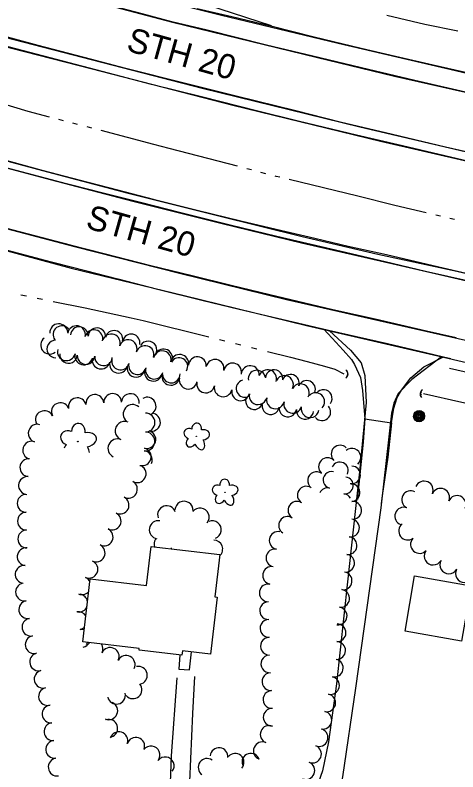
# Model space of a CAD drawing. Extents: x 588843 to 2552415, y 180129 to 269402.
# Drawn here: x 596827.9 to 597009.4, y 184077.1 to 184387.3 of the extents above; entities that cross this region are included whole.
import ezdxf

# ---------------------------------------------------------------- set-up
doc = ezdxf.new("R2010")
doc.units = 0
for name, color, linetype in [('Default', 7, 'Continuous'), ('E_BLD', 7, 'Continuous'), ('E_DRN', 7, 'Continuous'), ('E_DWY', 7, 'Continuous'), ('E_LAND_TreeLine_P', 7, 'Continuous'), ('E_LAND_Vegetation', 7, 'Continuous'), ('E_MISCPROP', 7, 'Continuous'), ('E_PATH_Sidewalk', 7, 'Continuous'), ('E_RDWY', 7, 'Continuous'), ('E_RDWY_Gravel', 7, 'Continuous'), ('E_RDWY_Text', 7, 'Continuous'), ('E_WTR_P', 7, 'Continuous')]:
    doc.layers.add(name, color=color, linetype=linetype)

# ---------------------------------------------------------------- blocks, each defined once
blk = doc.blocks.new('POLE')
at = {"layer": 'Default'}
for radius in [4.46, 3.35, 2.23, 1.12]:
    blk.add_circle((0, 0), radius, dxfattribs=at)
blk = doc.blocks.new('CULV2')
at = {"layer": 'E_DRN'}
blk.add_arc((19.7, 14.8), 24.6, 216.8699, 323.1301, dxfattribs=at)
blk = doc.blocks.new('DTRE')
at = {"layer": 'Default'}
blk.add_circle((-0.18, 0), 0.183, dxfattribs=at)
for centre, major_axis, ratio in [((-1.87, 5.32), (1.36, -4.98), 0.782863), ((4.06, 2.74), (-5.27, -2.93), 0.691916), ((-5.87, 0.15), (4.93, -0.12), 0.832022), ((-2.49, -5.24), (1.8, 4.86), 0.716896), ((3.54, -3.71), (-5.01, 4.58), 0.560249)]:
    blk.add_ellipse(centre, major_axis=major_axis, ratio=ratio, start_param=1.570796, end_param=4.712389, dxfattribs=at)
blk = doc.blocks.new('CULV2_4')
at = {"layer": 'E_DRN'}
blk.add_arc((65, 48), 80.7, 216.8699, 323.1301, dxfattribs=at)
blk = doc.blocks.new('POLE_3')
at = {"layer": 'E_MISCPROP'}
for radius in [14.6, 11, 7.32, 3.66]:
    blk.add_circle((0, 0), radius, dxfattribs=at)
blk = doc.blocks.new('DTRE_4')
at = {"layer": 'E_LAND_Vegetation'}
blk.add_circle((-0.6, 0), 0.601, dxfattribs=at)
for centre, major_axis, ratio in [((-6.1, 17.5), (4.5, -16.3), 0.782863), ((13.3, 9), (-17.3, -9.6), 0.691916), ((-19.3, 0.5), (16.2, -0.4), 0.832022), ((-8.2, -17.2), (5.9, 15.9), 0.716896), ((11.6, -12.2), (-16.4, 15), 0.560249)]:
    blk.add_ellipse(centre, major_axis=major_axis, ratio=ratio, start_param=1.570796, end_param=4.712389, dxfattribs=at)

msp = doc.modelspace()

# ---------------------------------------------------------------- linework, layer by layer
at = {"layer": 'E_BLD'}
for points in [[(596883.77, 184169.53), (596911.85, 184166.18), (596909.79, 184148.86), (596910.81, 184148.73), (596908.02, 184125.35), (596896.51, 184126.73), (596896.3, 184124.94), (596878.76, 184127.03), (596878.84, 184127.64), (596855.68, 184130.4), (596858.76, 184156.21), (596881.85, 184153.46)], [(597010.97, 184130.74), (596987.79, 184134.73), (596991.69, 184157.41), (597014.87, 184153.42)]]:
    msp.add_lwpolyline(points, close=True, dxfattribs=at)
at = {"layer": 'E_DWY'}
for points in [[(596954.33, 184258.7), (596957.91, 184254.93), (596962.44, 184250.04), (596965.86, 184246.21), (596967.08, 184244.07), (596969.51, 184238.75), (596970.35, 184233.4), (596971.32, 184221.9), (596982.29, 184220.26), (596983.2, 184226.22), (596984.61, 184230.54), (596986.35, 184233.61), (596990.14, 184238.65), (596995.44, 184243.18), (597003.56, 184247.25)], [(596956.85, 184257.89), (596965.4, 184249.99), (596969.75, 184244.8), (596971.27, 184239.65), (596971.88, 184228.55), (596969.06, 184200.1), (596964.26, 184154.96), (596959.64, 184113.14), (596956.45, 184089.42), (596953.89, 184077.51), (596950.34, 184067.35), (596946.51, 184058.42), (596942.86, 184053.96), (596937.47, 184048.93), (596929.11, 184045.67), (596919.51, 184044.02), (596912.14, 184046.27), (596905.02, 184048.65), (596903.2, 184050.84), (596900.38, 184060.03), (596899.5, 184073.2), (596900.78, 184101.02), (596901.62, 184116.24)], [(597002.73, 184247.31), (596990.58, 184237.99), (596985, 184232.28), (596983.25, 184228.24), (596982.22, 184224.11), (596977.82, 184185.38), (596967.46, 184111.39), (596962.14, 184075.02), (596959.65, 184064.88), (596955.17, 184049.82), (596949.6, 184038.43), (596946.07, 184031.73), (596941.32, 184027.48), (596936.01, 184024.63), (596926.24, 184023.87), (596918.41, 184025.61), (596911.03, 184028.17), (596904.65, 184033.62), (596899.86, 184041.04), (596894.78, 184051.17), (596891.23, 184061.51), (596891.99, 184083.69), (596894.43, 184115.71)], [(596971.32, 184221.9), (596970.57, 184212.24), (596968.5, 184191.1), (596968.24, 184188.79)], [(596982.29, 184220.26), (596980.77, 184206.14), (596978.4, 184190.36), (596977.99, 184187.08)]]:
    msp.add_lwpolyline(points, dxfattribs=at)
at = {"layer": 'E_LAND_TreeLine_P'}
for centre, radius, start, end in [((596845.83, 184257.15), 3.66, 2.2292, 182.2292), ((596847.1, 184256.38), 3.59, 36.9794, 216.9794), ((596853.08, 184256.3), 3.66, 349.694, 169.694), ((596854.24, 184255.99), 3.59, 356.2605, 176.2605), ((596861.41, 184255.52), 3.59, 356.2605, 176.2605), ((596860.23, 184254.69), 3.66, 346.488, 166.488), ((596867.34, 184252.95), 3.66, 341.2343, 161.2343), ((596868.49, 184254.45), 3.59, 348.3621, 168.3621), ((596875.53, 184253), 3.59, 348.3621, 168.3621), ((596842.09, 184252.05), 3.66, 127.6486, 307.6486), ((596844.57, 184250.48), 3.59, 90.4934, 270.4934), ((596874.28, 184250.59), 3.66, 340.5691, 160.5691), ((596882.46, 184250.11), 3.59, 328.9058, 148.9058), ((596848.94, 184249.37), 3.66, 166.3162, 346.3162), ((596881.21, 184248.19), 3.66, 343.0131, 163.0131), ((596888.23, 184246.08), 3.66, 346.8467, 166.8467), ((596888.84, 184246.84), 3.59, 334.0565, 154.0565), ((596849.83, 184248.2), 3.59, 176.1983, 356.1983), ((596856.06, 184247.63), 3.66, 166.3162, 346.3162), ((596856.99, 184247.73), 3.59, 176.1983, 356.1983), ((596863.19, 184245.93), 3.66, 166.8188, 346.8188), ((596864.16, 184247.25), 3.59, 176.1983, 356.1983), ((596871.11, 184245.48), 3.59, 164.9724, 344.9724), ((596895.4, 184244.56), 3.66, 350.5865, 170.5865), ((596895.1, 184243.31), 3.59, 330.5118, 150.5118), ((596902.65, 184243.59), 3.66, 355.619, 175.619), ((596909.9, 184242.53), 3.66, 348.0441, 168.0441), ((596870.33, 184244.26), 3.66, 166.8188, 346.8188), ((596877.47, 184242.59), 3.66, 167.0598, 347.0598), ((596878.05, 184243.61), 3.59, 164.9724, 344.9724), ((596917.08, 184241.03), 3.66, 349.5821, 169.5821), ((596924.32, 184239.97), 3.66, 356.1401, 176.1401), ((596884.61, 184240.95), 3.66, 167.0598, 347.0598), ((596884.99, 184241.75), 3.59, 164.9724, 344.9724), ((596891.76, 184239.31), 3.66, 167.5548, 347.5548), ((596891.95, 184240.15), 3.59, 181.2473, 1.2473), ((596927.05, 184238.22), 3.54, 9.5649, 189.5649), ((596931.44, 184238.3), 3.66, 342.0174, 162.0174), ((596934.09, 184238.39), 3.54, 356.2374, 176.2374), ((596940.87, 184236.49), 3.54, 340.7339, 160.7339), ((596898.91, 184237.73), 3.66, 167.5548, 347.5548), ((596906.07, 184236.15), 3.66, 167.5548, 347.5548), ((596922.1, 184234.21), 3.54, 105.1272, 285.1272), ((596938.36, 184235.91), 3.66, 332.6239, 152.6239), ((596947.5, 184233.99), 3.54, 337.8382, 157.8382), ((596913.23, 184234.56), 3.66, 167.2704, 347.2704), ((596920.38, 184232.94), 3.66, 167.2704, 347.2704), ((596944.86, 184232.53), 3.66, 332.2458, 152.2458), ((596954.33, 184230.27), 3.54, 323.5105, 143.5105), ((596860.62, 184228.15), 3.66, 2.983, 182.983), ((596867.92, 184228.53), 3.66, 2.983, 182.983), ((596875.21, 184228.49), 3.66, 353.5875, 173.5875), ((596882.05, 184227.02), 3.66, 299.548, 119.548), ((596927.52, 184231.31), 3.66, 166.7899, 346.7899), ((596951.17, 184228.87), 3.66, 315.6331, 135.6331), ((596846.48, 184224.77), 3.66, 26.5352, 206.5352), ((596853.45, 184226.8), 3.66, 12.499, 192.499), ((596876.13, 184223.81), 3.87, 49.1269, 229.1269), ((596925.95, 184229.21), 3.54, 160.5571, 340.5571), ((596932.7, 184227.11), 3.54, 172.4552, 352.4552), ((596934.66, 184229.63), 3.66, 166.7899, 346.7899), ((596941.76, 184227.8), 3.66, 164.9872, 344.9872), ((596839.93, 184221.5), 3.66, 26.5352, 206.5352), ((596939.73, 184226.18), 3.54, 172.4552, 352.4552), ((596946.76, 184225.27), 3.54, 173.759, 353.759), ((596948.85, 184225.98), 3.66, 170.1016, 350.1016), ((596953.75, 184224.67), 3.54, 220.8579, 40.8579), ((596881.36, 184220.32), 3.87, 270.1198, 90.1198), ((596883.82, 184220.43), 3.66, 255.0419, 75.0419), ((596836.97, 184215.93), 3.66, 71.9454, 251.9454), ((596872.8, 184216.9), 3.87, 67.7528, 247.7528), ((596881.31, 184212.59), 3.87, 262.3167, 82.3167), ((596881.93, 184213.36), 3.66, 255.0419, 75.0419), ((596834.7, 184208.98), 3.66, 71.9454, 251.9454), ((596869.87, 184209.75), 3.87, 67.7528, 243.9363), ((596880.04, 184206.3), 3.66, 255.0419, 75.0419), ((596961.15, 184207.39), 3.64, 45.1903, 225.1903), ((596966.02, 184206.06), 3.64, 310.1677, 130.1677), ((596880.28, 184204.93), 3.87, 338.7793, 82.3167), ((596956.01, 184202.22), 3.64, 45.1903, 225.1903), ((596833.57, 184201.8), 3.66, 85.5021, 265.5021), ((596961.05, 184200.66), 3.43, 334.313, 154.313), ((596877.96, 184199.32), 3.66, 240.7485, 60.7485), ((596951.5, 184196.5), 3.64, 52.7466, 232.7466), ((596957.62, 184196.78), 3.43, 76.8362, 256.8362), ((596965.83, 184198.84), 3.64, 267.0768, 87.0768), ((596832.99, 184194.51), 3.66, 85.5021, 265.5021), ((596963.14, 184194.54), 3.43, 263.4115, 83.4115), ((596874.38, 184192.94), 3.66, 240.7485, 60.7485), ((596947.3, 184190.56), 3.64, 58.212, 238.212), ((596956.05, 184190.1), 3.43, 76.8362, 156.5505), ((596965.64, 184191.56), 3.64, 275.4025, 95.4025), ((596995.63, 184192.61), 3.68, 336.3124, 156.3124), ((596832.45, 184187.22), 3.66, 91.0738, 271.0738), ((596962.35, 184187.72), 3.43, 27.0862, 83.4115), ((596990.08, 184188.7), 3.68, 61.7437, 241.7437), ((597002.37, 184189.65), 3.68, 336.3124, 156.3124), ((597009.1, 184186.7), 3.68, 336.3124, 156.3124), ((596870.96, 184186.48), 3.66, 243.4051, 63.4051), ((596897.19, 184184.32), 3.72, 356.8128, 176.8128), ((596943.46, 184184.36), 3.64, 58.212, 238.212), ((596966.32, 184184.31), 3.64, 275.4025, 95.4025), ((596890.07, 184182.49), 3.72, 19.1403, 199.1403), ((596903.74, 184181.54), 3.72, 322.299, 142.299), ((596987.29, 184181.91), 3.68, 69.9125, 249.9125), ((596832.59, 184179.92), 3.66, 91.0738, 271.0738), ((596867.69, 184179.94), 3.66, 243.4051, 63.4051), ((596939.62, 184178.17), 3.64, 58.212, 238.212), ((596886.65, 184176.37), 3.72, 80.0756, 260.0756), ((596908.74, 184176.32), 3.72, 291.0172, 111.0172), ((596965.44, 184177.09), 3.64, 262.0115, 82.0115), ((596988.89, 184175.84), 3.68, 127.4013, 307.4013), ((596832.72, 184172.61), 3.66, 91.0738, 271.0738), ((596864.41, 184173.41), 3.66, 243.4051, 63.4051), ((596935.79, 184171.97), 3.64, 79.2681, 259.2681), ((596888.6, 184170.48), 3.72, 148.0436, 197.32), ((596909.31, 184168.43), 3.72, 311.7625, 89.4794), ((596964.43, 184169.87), 3.64, 262.0115, 82.0115), ((596993.73, 184170.35), 3.68, 138.5447, 318.5447), ((596832.46, 184165.31), 3.66, 83.4786, 263.4786), ((596861.14, 184166.87), 3.66, 243.4051, 63.4051), ((596895.6, 184168.36), 3.72, 170.8115, 176.8493), ((596895.6, 184168.36), 3.72, 349.5518, 350.8115), ((596902.95, 184167.17), 3.72, 170.8115, 172.0696), ((596934.44, 184164.81), 3.64, 79.2681, 259.2681), ((596963.42, 184162.65), 3.64, 262.0115, 82.0115), ((596999.34, 184165.61), 3.68, 150.687, 330.687), ((596858.19, 184160.18), 3.66, 247.1166, 67.1166), ((597005.75, 184162.01), 3.68, 150.687, 330.687), ((596831.63, 184158.05), 3.66, 83.4786, 263.4786), ((596933.08, 184157.64), 3.64, 79.2681, 259.2681), ((597012.16, 184158.41), 3.68, 150.687, 330.687), ((596855.35, 184153.44), 3.66, 26.3818, 67.1166), ((596962.4, 184155.43), 3.64, 262.0115, 82.0115), ((596831.77, 184150.82), 3.66, 100.5014, 280.5014), ((596931.72, 184150.48), 3.64, 79.2681, 259.2681), ((596855.35, 184153.44), 3.66, 247.1166, 320.0193), ((596961.39, 184148.21), 3.64, 262.0115, 82.0115), ((596833.1, 184143.63), 3.66, 100.5014, 280.5014), ((596854.04, 184146.29), 3.66, 9.0275, 82.0718), ((596931.83, 184143.2), 3.64, 91.2868, 271.2868), ((596854.04, 184146.29), 3.66, 262.0718, 337.3736), ((596960.38, 184141), 3.64, 262.0115, 82.0115), ((596853.86, 184139.07), 3.66, 32.2653, 100.679), ((596834.44, 184136.44), 3.66, 100.5014, 280.5014), ((596931.99, 184135.91), 3.64, 91.2868, 271.2868), ((596959.9, 184134.13), 3.64, 268.7853, 88.7853), ((596853.86, 184139.07), 3.66, 280.679, 314.1358), ((596855.21, 184131.88), 3.66, 73.082, 100.679), ((596835.77, 184129.26), 3.66, 100.5014, 280.5014), ((596932.16, 184128.63), 3.64, 91.2868, 271.2868), ((596855.21, 184131.88), 3.66, 280.679, 330.3353), ((596860.3, 184127.54), 3.66, 134.5153, 154.0088), ((596860.3, 184127.54), 3.66, 334.0088, 31.8858), ((596959.75, 184126.85), 3.64, 268.7853, 88.7853), ((596837.58, 184122.17), 3.66, 104.4564, 284.4564), ((596866.91, 184124.42), 3.66, 335.4577, 155.4577), ((596873.45, 184121.15), 3.66, 332.8229, 152.8229), ((596932.35, 184121.34), 3.64, 93.4526, 273.4526), ((596958.78, 184119.66), 3.64, 257.6891, 77.6891), ((596878.45, 184116.66), 3.66, 282.0224, 102.0224), ((596839.4, 184115.09), 3.66, 104.4564, 284.4564), ((596932.79, 184114.07), 3.64, 93.4526, 273.4526), ((596957.23, 184112.53), 3.64, 257.6891, 77.6891), ((596876.28, 184110.77), 3.66, 220.2611, 40.2611), ((596841.23, 184108.01), 3.66, 104.4564, 284.4564), ((596933.23, 184106.79), 3.64, 93.4526, 273.4526), ((596869.48, 184108.55), 3.66, 191.9556, 11.9556), ((596955.68, 184105.41), 3.64, 257.6891, 77.6891), ((596842.67, 184100.87), 3.66, 95.8659, 275.8659), ((596866.32, 184102.16), 3.66, 246.6408, 66.6408), ((596933.32, 184099.5), 3.64, 90.6388, 270.6388), ((596954.12, 184098.29), 3.64, 257.6891, 77.6891), ((596843.42, 184093.59), 3.66, 95.8659, 275.8659), ((596866.32, 184094.97), 3.66, 288.2381, 108.2381), ((596932.1, 184092.47), 3.64, 67.3237, 247.3237), ((596952.55, 184091.18), 3.64, 248.2611, 68.2611), ((596870.44, 184089.86), 3.66, 341.9055, 161.9055), ((596877.39, 184087.58), 3.66, 341.9055, 161.9055), ((596844.17, 184086.32), 3.66, 95.8659, 275.8659), ((596929.29, 184085.74), 3.64, 67.3237, 247.3237), ((596883.66, 184084.03), 3.66, 322.4386, 142.4386), ((596911.55, 184083.33), 3.64, 354.0103, 174.0103), ((596949.85, 184084.4), 3.64, 248.2611, 68.2611), ((596845.18, 184079.08), 3.66, 98.1774, 278.1774), ((596889.45, 184079.57), 3.66, 322.4386, 142.4386), ((596906.64, 184078.94), 3.64, 54.8012, 234.8012), ((596918.12, 184081.01), 3.64, 318.988, 138.988), ((596924.58, 184081.05), 3.64, 18.6252, 198.6252), ((596947.15, 184077.63), 3.64, 248.2611, 68.2611)]:
    msp.add_arc(centre, radius, start, end, dxfattribs=at)
at = {"layer": 'E_LAND_Vegetation'}
msp.add_circle((596853.64, 184212.49), 0.128, dxfattribs=at)
for centre, major_axis, ratio, start_param, end_param in [((596853.8, 184216.39), (-0.29, -3.6), 0.782863, 1.570796, 4.712389), ((596849.93, 184213.94), (3.22, -1.25), 0.832022, 1.570796, 4.712389), ((596857.08, 184213.28), (-4.17, -0.67), 0.691916, 1.570796, 4.712389), ((596850.87, 184209.59), (2.34, 2.77), 0.716896, 1.570796, 2.052331), ((596855.21, 184209.16), (-2.21, 4.21), 0.560249, 4.154679, 4.712389)]:
    msp.add_ellipse(centre, major_axis=major_axis, ratio=ratio, start_param=start_param, end_param=end_param, dxfattribs=at)
at = {"layer": 'E_PATH_Sidewalk'}
msp.add_lwpolyline([(596895.44, 184125.04), (596895.11, 184119.25), (596899.43, 184118.9), (596900.23, 184126.28)], dxfattribs=at)
at = {"layer": 'E_RDWY'}
for points in [[(597032.69, 184351.08), (597016.17, 184354.94), (596991.76, 184360.55), (596972.87, 184365.01), (596950.02, 184370.52), (596930.95, 184375.07), (596906.62, 184381.14), (596892.19, 184384.61), (596880.05, 184387.83), (596860.19, 184393.05), (596830.91, 184400.75), (596818.75, 184404), (596788.82, 184412.15), (596765.6, 184418.74), (596743.28, 184424.94), (596706.19, 184435.62), (596685.24, 184441.92), (596658.8, 184449.78), (596634.24, 184457.17), (596618.91, 184461.89), (596609.39, 184464.84)], [(597026.93, 184328.01), (597025.37, 184328.37), (597004.37, 184333.27), (596982.69, 184338.46), (596961.21, 184343.5), (596942.96, 184348.08), (596918.49, 184354.07), (596898.33, 184359.15), (596873.34, 184365.52), (596856.22, 184369.91), (596837.32, 184374.86), (596818.07, 184380.05), (596797.15, 184385.68), (596775.05, 184391.82), (596753.46, 184397.93), (596735.61, 184402.94), (596720.37, 184407.31), (596697.21, 184414.05), (596679.57, 184419.25), (596655.28, 184426.51), (596637.24, 184431.81), (596614.68, 184438.77), (596602.46, 184442.59)], [(596933.09, 184382.94), (596837.87, 184413.93)], [(596831.75, 184400.44), (596858.75, 184393.38), (596892.45, 184384.48), (596919.43, 184377.87), (596951.34, 184370.1), (596983.45, 184362.27), (597016.79, 184354.74), (597046.68, 184347.63), (597079.81, 184340.05), (597123.33, 184329.81), (597158.41, 184321.69), (597191.53, 184314.11), (597231.88, 184304.53), (597278.69, 184293.59), (597318.11, 184284.48), (597364.49, 184273.87), (597407.26, 184263.94), (597449.32, 184254.1), (597493.42, 184244.01), (597537.64, 184233.58), (597587.58, 184222.19), (597639.5, 184210.36), (597689.48, 184198.75)], [(596815.1, 184380.55), (596855.37, 184370.13), (596904.64, 184357.46), (596969.32, 184341.58), (597021.23, 184329.33), (597056.25, 184321.02), (597109.12, 184308.82), (597158.76, 184297.1), (597205.08, 184286.29), (597251.45, 184275.68), (597292.62, 184266.4), (597342.16, 184254.71), (597389.87, 184243.62), (597437.19, 184232.64), (597472.2, 184224.65), (597520.55, 184213.6), (597569.33, 184202.21), (597631.03, 184188.1), (597685.98, 184175.44)], [(596807.31, 184329.2), (596842.23, 184319.94), (596876.16, 184311.09), (596912.83, 184301.9), (596945.36, 184294.06), (596984.2, 184285.11), (597027.27, 184275.1), (597066.2, 184266.12), (597109.25, 184256.43), (597150.88, 184246.92), (597194.98, 184236.83), (597236.5, 184227.67), (597275.02, 184218.71), (597315.1, 184209.31), (597376.66, 184195.45), (597431.4, 184183.15), (597485.2, 184170.91), (597526.83, 184161.4), (597571.25, 184151.33), (597617.09, 184141.08), (597657, 184131.83), (597684.02, 184125.73)], [(596811.2, 184328.28), (596828.22, 184323.76), (596844.82, 184319.45), (596863.48, 184314.66), (596879.94, 184310.49), (596895.82, 184306.38), (596916.1, 184301.31), (596935.22, 184296.66), (596961.62, 184290.52), (596979.68, 184286.33), (596996.23, 184282.42), (597014.51, 184278.26)], [(596813.68, 184302.57), (596852.3, 184292.45), (596895.32, 184281.51), (596939.25, 184270.83), (596989.1, 184259.47), (597040.33, 184247.83), (597085.56, 184237.65), (597127.55, 184227.93), (597167.69, 184218.73), (597214.72, 184207.83), (597265.96, 184196.19), (597303.87, 184187.71), (597352.3, 184176.53), (597403.95, 184164.88), (597455.48, 184153.16), (597504.06, 184142.15), (597550.85, 184131.53), (597599.74, 184120.53), (597645.79, 184109.91), (597674, 184103.58)], [(596821.08, 184300.89), (596835.83, 184296.97), (596850.52, 184293.19), (596864.48, 184289.56), (596883.54, 184284.74), (596900.48, 184280.55), (596916.5, 184276.69), (596932.33, 184272.88), (596946.77, 184269.4), (596958.24, 184266.72), (596975.49, 184262.78), (596982.01, 184261.29), (596996.6, 184257.98), (597008.75, 184255.18)]]:
    msp.add_lwpolyline(points, dxfattribs=at)
at = {"layer": 'E_RDWY_Gravel'}
for points in [[(597026.08, 184324.6), (597011.62, 184327.94), (596986.69, 184333.71), (596967.87, 184338.2), (596943.91, 184343.89), (596926.95, 184348.09), (596904.82, 184353.69), (596883.8, 184358.97), (596866.27, 184363.49), (596844.84, 184369.22), (596825.58, 184374.17), (596800.9, 184380.77), (596777.84, 184387.2), (596763.35, 184391.24), (596746.16, 184395.96), (596721.81, 184402.96), (596704.88, 184407.78), (596686.67, 184413.05), (596669.55, 184418.21), (596652.98, 184423.27), (596636.03, 184428.34), (596618.32, 184433.65), (596601.26, 184439.01)], [(596831.79, 184408.16), (596876.04, 184396.59), (596912.48, 184387.35), (596960.41, 184375.89), (597008.48, 184364.6), (597059.68, 184352.45), (597113.53, 184339.98), (597173.17, 184326.02), (597224.72, 184313.98), (597285, 184300.47), (597347.07, 184286.15), (597402.84, 184273.05), (597467.86, 184258.02), (597525.2, 184244.48), (597582.05, 184231.5), (597632.68, 184219.92), (597677.17, 184209.73), (597698.04, 184205.01)], [(596902.55, 184390.09), (596916.82, 184386.81), (596933.28, 184382.77), (596950.59, 184378.47), (596969.87, 184373.82), (596983.9, 184370.55), (596999.29, 184366.97), (597018.58, 184362.56), (597031.75, 184359.4), (597034.6, 184358.73)], [(596815.14, 184376.73), (596859.5, 184365.31), (596917.2, 184350.41), (596977.68, 184335.69), (597015.74, 184326.96), (597058.12, 184317.14), (597106.84, 184305.88), (597139.56, 184297.99), (597153.34, 184294.6), (597159.08, 184292.91), (597167, 184289.25), (597179.95, 184282.09), (597188.03, 184276.71), (597195.36, 184270.16), (597201.57, 184264.87), (597202.48, 184263.57), (597202.75, 184262.65), (597202.47, 184261.26), (597201.3, 184259.69), (597197.74, 184257.1), (597187.36, 184253.76), (597161.54, 184250.49), (597150.73, 184249.8)], [(596807.98, 184331.92), (596839.19, 184323.61), (596874.26, 184314.34), (596910.84, 184305.17), (596945.58, 184296.62), (596976.7, 184289.38), (597009.02, 184282.34), (597044.95, 184273.88), (597084.33, 184264.99), (597124.4, 184255.92), (597142.81, 184251.77), (597150.74, 184249.8)], [(596819.52, 184329.05), (596839.47, 184323.69), (596854.01, 184319.8), (596869.89, 184315.69), (596884.59, 184311.93), (596902.61, 184307.4), (596920.5, 184302.95), (596934.92, 184299.57), (596950.76, 184295.86), (596964.51, 184292.66), (596980.23, 184289.15), (596999.31, 184284.71), (597015.19, 184280.99)], [(596809.86, 184294.62), (596850.9, 184283.59), (596897.3, 184272.34), (596947.42, 184260.06), (596997.62, 184248.5), (597042.38, 184238.12), (597083.63, 184229.14), (597131.86, 184218.02), (597177.46, 184207.3), (597220.85, 184197.3), (597260.12, 184188.76), (597304.1, 184179.02), (597336.14, 184171.32), (597380.02, 184161.19), (597416.89, 184153.1), (597454.25, 184144.14), (597478.85, 184138.81), (597522.83, 184129.07), (597564.61, 184119.31), (597606.68, 184109.89), (597645.27, 184100.8), (597671.8, 184094.83)], [(596817.84, 184292.78), (596838.55, 184287.34), (596856.75, 184282.61), (596869.99, 184279.19), (596886.34, 184275.04), (596904.49, 184270.55), (596919.84, 184266.8), (596935.49, 184263.11), (596946.03, 184260.66), (596956.45, 184258.2), (596980.64, 184252.7), (596996.18, 184249.01), (597003.49, 184247.27), (597006.6, 184246.56)], [(597006.03, 184242.62), (597061.27, 184230.1), (597118.1, 184216.78), (597167.8, 184205.76), (597170.46, 184205.61)]]:
    msp.add_lwpolyline(points, dxfattribs=at)
at = {"layer": 'E_WTR_P'}
for points in [[(596980.34, 184387.35), (596995.88, 184383.65), (597009.38, 184380.89)], [(596841.98, 184345.57), (596833.34, 184347.84), (596814.2, 184353.52)], [(596847.76, 184344.06), (596845.83, 184344.56)], [(596853.54, 184342.54), (596851.62, 184343.05)], [(596859.33, 184341.03), (596857.4, 184341.53)], [(596891.14, 184332.69), (596884.8, 184334.35), (596863.18, 184340.02)], [(596919.09, 184325.37), (596891.14, 184332.69)], [(596924.87, 184323.86), (596922.95, 184324.36)], [(596930.66, 184322.35), (596928.73, 184322.85)], [(596936.45, 184320.86), (596935, 184321.21), (596934.51, 184321.34)], [(596968.39, 184313.06), (596940.32, 184319.91)], [(596996.49, 184306.31), (596983.65, 184309.34), (596968.39, 184313.06)], [(597002.31, 184304.94), (597000.37, 184305.4)], [(597008.13, 184303.57), (597006.19, 184304.03)], [(596830.32, 184272.73), (596832.53, 184272.27)], [(596836.94, 184271.36), (596839.15, 184270.9)], [(596843.57, 184269.99), (596856.6, 184267.3), (596875.56, 184263.23)], [(596875.56, 184263.23), (596880.41, 184262.18), (596907.31, 184255.45)], [(596911.69, 184254.36), (596913.87, 184253.81)], [(596918.25, 184252.72), (596920.44, 184252.19)], [(596924.82, 184251.11), (596927.01, 184250.57)], [(596931.38, 184249.49), (596940.81, 184247.17), (596947.68, 184245.38), (596954.71, 184243.43), (596958.98, 184242.15), (596962.67, 184240.29)], [(596995.34, 184232.2), (597011.08, 184228.69), (597020.03, 184226.7)]]:
    msp.add_lwpolyline(points, dxfattribs=at)

# ---------------------------------------------------------------- block references
at = {"layer": 'E_DRN'}
for name, p, xscale, yscale, rotation in [('CULV2_4', (596963.48, 184238.48), 0.025880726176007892, 0.025880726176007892, 88.5842540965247), ('CULV2', (596963.95, 184239.45), 0.039742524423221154, 0.03974252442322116, 84.65422196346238), ('CULV2_4', (596994.95, 184233.67), 0.023747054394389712, 0.023747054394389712, -97.85734601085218), ('CULV2', (596994.55, 184232.84), 0.034255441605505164, 0.03425544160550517, -92.9527200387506)]:
    msp.add_blockref(name, p, dxfattribs=dict(at, xscale=xscale, yscale=yscale, rotation=rotation))
at = {"layer": 'E_LAND_Vegetation'}
for name, p, xscale, yscale, rotation in [('DTRE', (596902.31, 184214.67), 0.4999999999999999, 0.4999999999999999, -19.880233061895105), ('DTRE_4', (596914.03, 184191.72), 0.1524003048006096, 0.15240030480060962, -15.451989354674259)]:
    msp.add_blockref(name, p, dxfattribs=dict(at, xscale=xscale, yscale=yscale, rotation=rotation))
at = {"layer": 'E_MISCPROP'}
for name, p, xscale, yscale, rotation in [('POLE', (596993.58, 184223.01), 0.4999999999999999, 0.4999999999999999, -19.880233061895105), ('POLE_3', (596993.54, 184222.86), 0.1524003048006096, 0.15240030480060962, -15.451989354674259)]:
    msp.add_blockref(name, p, dxfattribs=dict(at, xscale=xscale, yscale=yscale, rotation=rotation))

# ---------------------------------------------------------------- texts
at = {"layer": 'E_RDWY_Text'}
for p in [(596873.09, 184372.86), (596856.43, 184300.15)]:
    msp.add_text('STH 20', height=10, rotation=344.3356, dxfattribs=at).set_placement(p)

doc.saveas('drawing.dxf')
